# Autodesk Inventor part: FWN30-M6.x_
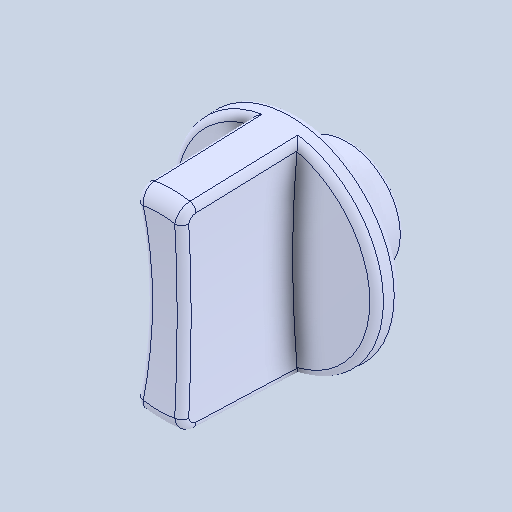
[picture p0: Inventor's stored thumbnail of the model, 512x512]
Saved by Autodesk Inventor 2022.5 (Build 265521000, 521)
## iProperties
Created: 2024-09
Part Number: FWN30-M6.x_
Material: 一般
Document SubType Name: Modeling
Designer: ImaoCorp
Density: 1 g/cm^3
Appearance: 既定
Author: ImaoCorp
Sending System: SOLIDWORKS 2022-2022290
MC: AMD64
MC_MODEL: Intel64 Family 6 Model 60 Stepping 3, GenuineIntel
OS: Windows_NT
FRU: Parasolid Version 33.1, build 260,  4-25-2022
FORMAT: text
GUISE: transmit
KEY: FILEFWN30-M6.x_t
DATE: Tue Sep  3 09:30:13 2024
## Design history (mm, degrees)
feature "Base1"
node "ソリッド1"
